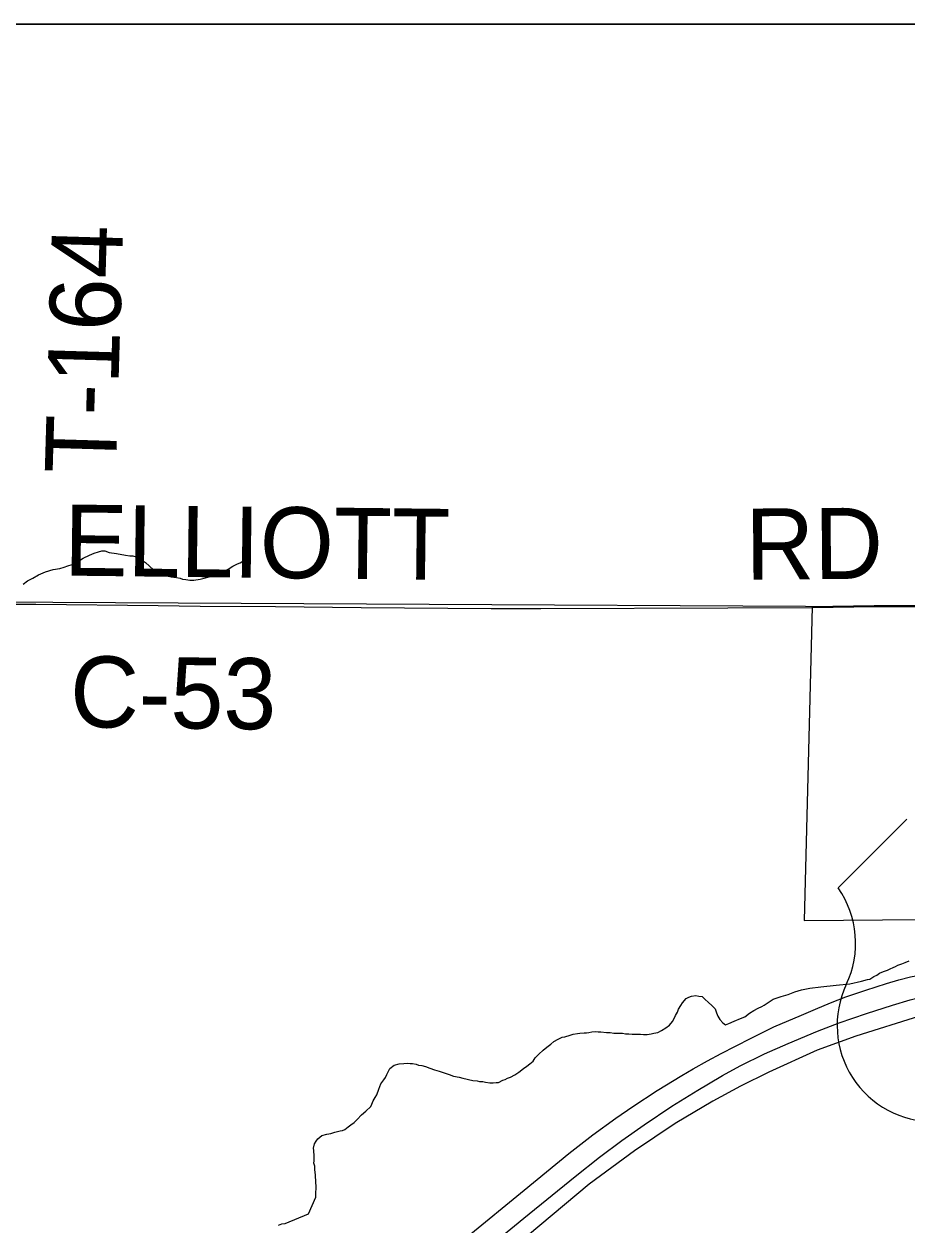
# Model space of a CAD drawing. Extents: x 0 to 34, y 0 to 22.
# Drawn here: x 5.51 to 6.216, y 19.941 to 20.9 of the extents above; entities that cross this region are included whole.
import ezdxf

# ---------------------------------------------------------------- set-up
doc = ezdxf.new("R2010")
doc.units = 0
for name, color, linetype in [('Default', 7, 'Continuous'), ('GM_X_County_Road', 7, 'Continuous'), ('GM_X_County_Road_Text', 7, 'Continuous'), ('GM_X_Minor_River', 7, 'Continuous'), ('GM_X_Section', 7, 'Continuous'), ('GM_X_Township_Road', 7, 'Continuous'), ('GM_X_Township_Road_Text', 7, 'Continuous'), ('GM_X_US_Route', 7, 'Continuous'), ('GM_X_US_Shield', 7, 'Continuous'), ('SH_Data', 7, 'Continuous')]:
    doc.layers.add(name, color=color, linetype=linetype)

msp = doc.modelspace()

# ---------------------------------------------------------------- linework, layer by layer
at = {"layer": 'Default'}
msp.add_lwpolyline([(6.49402, 20.9), (5.49304, 20.9), (5.48293, 20.43816), (6.48534, 20.43303)], close=True, dxfattribs=at)
for points in [[(6.26978, 20.43556), (6.18963, 20.43507), (6.14, 20.43428), (6.13367, 20.18377), (6.22753, 20.18449)], [(6.22582, 20.10729), (6.1749, 20.09133), (6.14393, 20.07995), (6.10531, 20.06255), (6.08285, 20.05135), (6.06072, 20.03938), (6.03062, 20.0214), (5.99797, 19.99956), (5.96195, 19.97292), (5.91265, 19.93164)]]:
    msp.add_lwpolyline(points, dxfattribs=at)
at = {"layer": 'GM_X_County_Road'}
for points in [[(5.48185, 20.43639), (5.48749, 20.43638), (5.51987, 20.43632), (5.61747, 20.43539), (5.65104, 20.43489), (5.71134, 20.43457), (5.77972, 20.43384), (5.88352, 20.43283), (5.92331, 20.43291), (6.0725, 20.43358), (6.14024, 20.43373)], [(6.14024, 20.43373), (6.18986, 20.43451), (6.27002, 20.43501), (6.27101, 20.43502)]]:
    msp.add_lwpolyline(points, dxfattribs=at)
at = {"layer": 'GM_X_Minor_River'}
for points in [[(5.50969, 20.45249), (5.51317, 20.45506), (5.5174, 20.45723), (5.52203, 20.45977), (5.52741, 20.46229), (5.53353, 20.46403), (5.53887, 20.46503), (5.54232, 20.46608), (5.54539, 20.46715), (5.54883, 20.4682), (5.55075, 20.46891), (5.55383, 20.47073), (5.5577, 20.47329), (5.56269, 20.47544), (5.56653, 20.47724), (5.56998, 20.47829), (5.57266, 20.47898), (5.57493, 20.47892), (5.57832, 20.4777), (5.58438, 20.47679), (5.59156, 20.47546), (5.59497, 20.475), (5.59725, 20.47494), (5.59988, 20.47412), (5.60177, 20.47369), (5.60513, 20.47133), (5.60737, 20.46975), (5.61368, 20.4639), (5.61707, 20.46267), (5.61931, 20.46109), (5.62156, 20.4599), (5.62457, 20.45906), (5.62797, 20.45822), (5.63214, 20.45773), (5.63517, 20.45728), (5.63704, 20.45647), (5.63969, 20.45602), (5.64272, 20.45557), (5.64614, 20.45548), (5.6511, 20.45649), (5.65416, 20.45718), (5.65721, 20.45786), (5.66066, 20.45891), (5.6641, 20.45996), (5.6664, 20.46066), (5.66949, 20.46248), (5.67333, 20.46428), (5.67719, 20.46684), (5.68104, 20.46864), (5.68296, 20.46935), (5.68682, 20.47191), (5.68875, 20.473), (5.68874, 20.47262), (5.68875, 20.473)], [(5.95964, 20.09394), (5.96155, 20.09426), (5.96384, 20.09458), (5.96726, 20.09486), (5.96916, 20.0948), (5.97106, 20.09475), (5.9756, 20.09424), (5.97864, 20.09415), (5.98166, 20.09368), (5.98432, 20.09361), (5.9866, 20.09354), (5.9885, 20.09349), (5.99076, 20.09304), (5.99342, 20.09296), (5.99608, 20.09289), (5.99911, 20.0928), (6.00291, 20.09269), (6.00518, 20.09263), (6.00822, 20.09254), (6.01128, 20.09321), (6.01357, 20.09352), (6.01662, 20.0942), (6.01971, 20.09563), (6.02319, 20.09781), (6.02591, 20.10001), (6.02828, 20.10298), (6.02986, 20.10522), (6.0307, 20.10785), (6.03229, 20.11047), (6.03312, 20.11272), (6.03511, 20.1157), (6.03631, 20.11795), (6.03945, 20.12128), (6.04138, 20.12237), (6.04368, 20.12306), (6.04712, 20.12372), (6.04939, 20.12328), (6.05203, 20.12282), (6.05425, 20.12085), (6.05721, 20.11811), (6.0598, 20.11575), (6.06238, 20.11302), (6.06343, 20.10995), (6.06449, 20.10726), (6.06631, 20.10455), (6.06851, 20.10182), (6.07074, 20.10024), (6.07343, 20.1013), (6.07766, 20.10308), (6.08266, 20.10522), (6.08612, 20.10664), (6.09001, 20.10956), (6.09349, 20.11174), (6.09696, 20.11354), (6.09966, 20.11499), (6.10159, 20.11607), (6.10895, 20.1208), (6.11509, 20.1229), (6.12084, 20.12464), (6.12621, 20.12676), (6.13157, 20.12813), (6.13807, 20.12946), (6.14684, 20.13073), (6.15903, 20.1319), (6.17008, 20.1331), (6.17926, 20.13512), (6.18424, 20.13649), (6.18614, 20.13682), (6.18925, 20.13901), (6.19156, 20.14009), (6.19388, 20.14154), (6.19696, 20.14297), (6.20003, 20.14402), (6.20234, 20.14509), (6.20465, 20.14617), (6.20657, 20.14687), (6.2085, 20.14796), (6.21157, 20.14901), (6.21426, 20.15007), (6.21734, 20.1515)], [(5.73755, 19.94923), (5.74346, 19.96258), (5.74352, 19.96448), (5.74358, 19.96676), (5.74365, 19.96904), (5.74373, 19.97169), (5.74342, 19.97398), (5.74348, 19.97626), (5.74317, 19.97855), (5.74323, 19.98045), (5.7429, 19.98236), (5.74259, 19.98465), (5.74267, 19.98731), (5.74197, 19.98961), (5.74203, 19.99151), (5.74214, 19.9953), (5.74189, 19.99987), (5.74157, 20.00178), (5.74243, 20.00518), (5.74364, 20.00742), (5.74521, 20.00928), (5.74832, 20.01185), (5.75215, 20.01288), (5.75559, 20.01354), (5.75866, 20.01459), (5.76287, 20.01561), (5.76478, 20.01594), (5.7667, 20.01664), (5.76942, 20.01884), (5.77136, 20.02031), (5.77407, 20.02213), (5.77643, 20.02472), (5.77996, 20.02842), (5.78346, 20.03136), (5.78736, 20.03505), (5.78818, 20.03692), (5.7894, 20.03955), (5.79099, 20.04216), (5.7922, 20.04441), (5.79385, 20.04892), (5.79549, 20.05306), (5.79787, 20.05641), (5.79906, 20.05827), (5.80027, 20.06052), (5.80148, 20.06314), (5.80269, 20.06539), (5.80618, 20.06795), (5.81001, 20.06898), (5.81382, 20.06925), (5.81686, 20.06954), (5.81876, 20.06949), (5.82066, 20.06943), (5.82368, 20.06897), (5.82556, 20.06815), (5.82821, 20.0677), (5.83122, 20.06685), (5.8346, 20.06561), (5.83836, 20.06436), (5.84213, 20.06312), (5.84589, 20.06187), (5.85003, 20.06061), (5.85341, 20.05937), (5.85794, 20.05848), (5.86096, 20.05763), (5.86888, 20.05588), (5.87229, 20.05541), (5.87417, 20.05497), (5.87683, 20.0549), (5.8791, 20.05445), (5.8825, 20.05397), (5.88516, 20.0539), (5.88745, 20.05421), (5.88934, 20.05416), (5.89281, 20.05596), (5.89474, 20.05666), (5.89667, 20.05774), (5.89896, 20.05844), (5.90244, 20.06024), (5.90554, 20.06243), (5.90943, 20.06536), (5.91214, 20.06718), (5.91447, 20.06902), (5.91719, 20.07122), (5.91879, 20.07383), (5.92153, 20.07679), (5.92505, 20.08011), (5.92815, 20.0823), (5.93127, 20.08487), (5.93361, 20.08709), (5.93708, 20.08888), (5.94016, 20.09032), (5.94245, 20.09063), (5.94667, 20.09203), (5.94897, 20.09272), (5.95241, 20.09338), (5.95432, 20.09371), (5.95774, 20.09399), (5.95964, 20.09394)], [(5.7136, 19.94015), (5.71629, 19.94122), (5.71896, 19.94153), (5.73755, 19.94923)]]:
    msp.add_lwpolyline(points, dxfattribs=at)
at = {"layer": 'GM_X_Section'}
msp.add_lwpolyline([(5.48293, 20.43816), (6.48534, 20.43303), (6.46596, 19.43025), (5.4561, 19.43741)], close=True, dxfattribs=at)
at = {"layer": 'GM_X_Township_Road'}
msp.add_lwpolyline([(7.49369, 20.9), (2.1, 20.9)], dxfattribs=at)
at = {"layer": 'GM_X_US_Route'}
for points in [[(5.86436, 19.9308), (5.9099, 19.96828), (5.94566, 19.99738), (5.96465, 20.01226), (5.98306, 20.02566), (5.99662, 20.03503), (6.01603, 20.04769), (6.03578, 20.0598), (6.04483, 20.06506), (6.05625, 20.07164), (6.06718, 20.07748), (6.07886, 20.08331), (6.09119, 20.08956), (6.10944, 20.09876), (6.13158, 20.10788), (6.14253, 20.11279), (6.15465, 20.11798), (6.16688, 20.12256), (6.18288, 20.12809), (6.19929, 20.13321), (6.20924, 20.13618), (6.21866, 20.1386), (6.22713, 20.14036)], [(5.89177, 19.93103), (5.90961, 19.94573), (5.95062, 19.97901), (5.97006, 19.99449), (5.98793, 20.00795), (6.00571, 20.02048), (6.02799, 20.03522), (6.04853, 20.04808), (6.05712, 20.05308), (6.06835, 20.05987), (6.08239, 20.06748), (6.10198, 20.07699), (6.12071, 20.08542), (6.14427, 20.09519), (6.16167, 20.10198), (6.18346, 20.10945), (6.20423, 20.11595), (6.2184, 20.12018), (6.22687, 20.12247)]]:
    msp.add_lwpolyline(points, dxfattribs=at)
at = {"layer": 'GM_X_US_Shield'}
msp.add_line((6.21573, 20.26462), (6.1608, 20.20969), dxfattribs=at)
for centre, start, end in [((6.0978, 20.16557), 334.54712, 35.00093), ((6.23685, 20.09982), 154.83192, 270.63826)]:
    msp.add_arc(centre, 0.0769, start, end, dxfattribs=at)
at = {"layer": 'SH_Data'}
msp.add_line((2.1, 20.9), (8.9, 20.9), dxfattribs=at)

# ---------------------------------------------------------------- texts
at = {"layer": 'GM_X_County_Road_Text'}
for s, rotation, p in [('ELLIOTT', 359.33294, (5.54216, 20.45927)), ('RD', 0.48499, (6.08693, 20.45592)), ('C-53', 359.3144, (5.54693, 20.33821))]:
    msp.add_text(s, height=0.056818, rotation=rotation, dxfattribs=at).set_placement(p)
at = {"layer": 'GM_X_Township_Road_Text'}
msp.add_text('T-164', height=0.056818, rotation=88.31515, dxfattribs=at).set_placement((5.58372, 20.54007))

doc.saveas('drawing.dxf')
